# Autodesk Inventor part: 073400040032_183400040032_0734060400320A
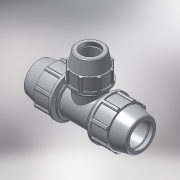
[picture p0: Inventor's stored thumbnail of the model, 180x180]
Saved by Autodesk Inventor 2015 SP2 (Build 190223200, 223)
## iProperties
Created: 2017-02
Part Number: 073400040032_183400040032_0734060400320A
Material: PVC-Piping
Description: PLASSON REDUCING TEE 40-32-40
Document SubType Name: Modeling
Designer: KIM
Mass: 92.6774 g
Surface Area: 199.44 cm^2
Volume: 66.1981 cm^3
Density: 1.4 g/cm^3
Appearance: Smooth - White
Author: Кирилл
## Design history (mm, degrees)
derived "07340.ipt"
feature "Solid1::07340.ipt"
feature "Solid2::07340.ipt"
tag "TaggingFeature1"
body "Solid1"
other parameters: "d4" = 8.625, "d5" = 28.98, "d7" = 82, "d11" = 3.45, "d13" = 120 deg, "d15" = 12 deg, "d16" = 71.34, "d18" = 2, "d19" = 35 deg, "d20" = 17.5 deg, "d21" = 76.26, "d23" = 0, "d25" = 360 deg, "d27" = 1.64, "d33" = 0.8, "d42" = 37.26, "d43" = 2.46, "d46" = 1.2, "d67" = 61.5, "d76" = 32, "d77" = 64, "d78" = 12 deg, "d79" = 97, "d80" = 120 deg, "d81" = 48, "d82" = 8.08333, "d87" = 3.23333, "d89" = 24.25, "d90" = 29.1, "d96" = 17.25, "d98" = 59.52, "d99" = 35 deg, "d100" = 17.5 deg, "d102" = 0, "d103" = 1.28, "d107" = 360 deg, "d109" = 0.96, "d112" = 1.6, "d113" = 4.26667, "d114" = 0, "d117" = 207, "d118" = 55.68, "d126" = 36, "d127" = 82, "d131" = 3.88, "d132" = 28.8, "d133" = 67, "d135" = 0, "d138" = 4.14, "d143" = 0, "d148" = 48, "d168" = 36, "d170" = 0, "d171" = 32, "d173" = 0, "d175" = 0, "d176" = 4.26667, "d177" = 0, "E_" = 82, "A_" = 97, "l_" = 82, "E_1" = 64, "l_1" = 67, "d_1" = 32, "H_" = 207
